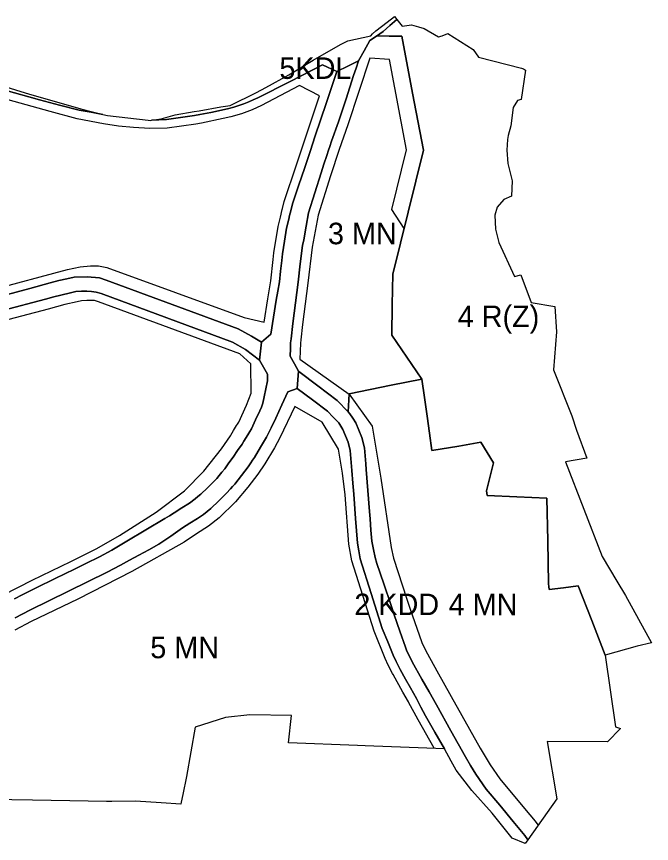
# Model space of a CAD drawing. Extents: x 7422252 to 7424226, y 5538569 to 5540380.
# Drawn here: x 7423783 to 7424226, y 5538929 to 5539505 of the extents above; entities that cross this region are included whole.
import ezdxf

# ---------------------------------------------------------------- set-up
doc = ezdxf.new("R2010")
doc.units = 0
for name, color, linetype in [('linie_rozgraniczajace', 7, 'Continuous'), ('linie_zabudowy_nieprzekraczalne', 7, 'Continuous'), ('oznaczenia_przeznaczen', 7, 'Continuous')]:
    doc.layers.add(name, color=color, linetype=linetype)

msp = doc.modelspace()

# ---------------------------------------------------------------- linework, layer by layer
at = {"layer": 'linie_rozgraniczajace'}
for points in [[(7423877.24, 5539432.91), (7423884.04, 5539433.94), (7423893.8, 5539436.72), (7423907.13, 5539439), (7423910.44, 5539439.57), (7423925.6, 5539442.23), (7423932.04, 5539443.25), (7423950.6, 5539452.2), (7423956.96, 5539455.69), (7423973.09, 5539464.55), (7423989.94, 5539474.71), (7424008.95, 5539485.69), (7424014.17, 5539488.19), (7424030.09, 5539491.68), (7424031.22, 5539493.04), (7424033.58, 5539495.28), (7424041.52, 5539501.38), (7424046.6, 5539505.19), (7424048.26, 5539503.12), (7424043.49, 5539498.95), (7424038.71, 5539494.78), (7424036.4, 5539493.2), (7424034.09, 5539491.61), (7424029.46, 5539488.45), (7424025.55, 5539481.36), (7424021.63, 5539474.27), (7424014.05, 5539470.55), (7424006.46, 5539466.83), (7423996.59, 5539471.45), (7423973.97, 5539460.04), (7423951.36, 5539448.64), (7423948.2, 5539447.17), (7423945.05, 5539445.7), (7423941.66, 5539444.42), (7423938.27, 5539443.13), (7423934.73, 5539442.15), (7423931.2, 5539441.18), (7423926.04, 5539439.92), (7423918.57, 5539438.38), (7423911.09, 5539436.83), (7423907.19, 5539436.17), (7423897.49, 5539434.75), (7423887.78, 5539433.34), (7423882.51, 5539433.13)], [(7424034.09, 5539491.61), (7424036.4, 5539493.2), (7424038.71, 5539494.78), (7424043.49, 5539498.95), (7424048.26, 5539503.12), (7424052.01, 5539498.44), (7424058.53, 5539499.41), (7424063.33, 5539498.06), (7424067.26, 5539496.94), (7424077.38, 5539491.11), (7424079.81, 5539491.64), (7424083.86, 5539493.27), (7424101.44, 5539482.17), (7424105.16, 5539476.82), (7424135.25, 5539469.27), (7424136.57, 5539468.64), (7424137.97, 5539467.89), (7424134.91, 5539447.36), (7424132.45, 5539446.59), (7424129.29, 5539441.9), (7424127.67, 5539429.1), (7424125.94, 5539422.32), (7424125.37, 5539419.48), (7424124.96, 5539412.17), (7424125.62, 5539402.78), (7424128.75, 5539390.8), (7424128.28, 5539379.93), (7424122.91, 5539377.72), (7424118.28, 5539372.37), (7424116.56, 5539366.83), (7424117.11, 5539357.13), (7424119.42, 5539347.81), (7424130.29, 5539324.12), (7424134.78, 5539325.3), (7424141.78, 5539306.02), (7424158.37, 5539303.13), (7424159.61, 5539285.56), (7424157.46, 5539259.07), (7424170.12, 5539227.02), (7424173.53, 5539216.86), (7424180.64, 5539197.37), (7424165.8, 5539195.01), (7424191.4, 5539128.84), (7424201.62, 5539111.65), (7424207.53, 5539101.69), (7424225.71, 5539068.74), (7424215.75, 5539066.44), (7424193.55, 5539060.17), (7424184.06, 5539084.3), (7424174.57, 5539108.42), (7424164.46, 5539107.21), (7424154.35, 5539106.01), (7424154.21, 5539108), (7424154.07, 5539110), (7424153.39, 5539139.85), (7424152.72, 5539169.7), (7424131.94, 5539170.57), (7424111.17, 5539171.43), (7424110.77, 5539174.68), (7424111.35, 5539177.51), (7424113.47, 5539185.9), (7424115.6, 5539194.29), (7424111.16, 5539201.46), (7424106.73, 5539208.62), (7424091.39, 5539205.92), (7424072.78, 5539202.9), (7424071.13, 5539214.87), (7424069.48, 5539226.84), (7424067.57, 5539239.68), (7424065.65, 5539252.53), (7424055.21, 5539267.88), (7424044.78, 5539283.22), (7424045.11, 5539304.41), (7424045.45, 5539325.59), (7424056.11, 5539368.85), (7424066.77, 5539412.1), (7424059.26, 5539451.8), (7424051.75, 5539491.49), (7424042.95, 5539491.57), (7424035.58, 5539491.63)], [(7423973.86, 5539268.46), (7423974.25, 5539273.94), (7423974.28, 5539277.87), (7423974.55, 5539280.73), (7423975.87, 5539291.33), (7423977.65, 5539305.74), (7423979.44, 5539320.16), (7423981.02, 5539332.92), (7423982.6, 5539345.68), (7423983.45, 5539349.61), (7423985.15, 5539359.04), (7423986.85, 5539368.46), (7423991.18, 5539382.32), (7423995.51, 5539396.19), (7423997.52, 5539402.3), (7423999.53, 5539408.42), (7424000.73, 5539412.05), (7424001.57, 5539414.6), (7424002.85, 5539418.39), (7424007.75, 5539431.82), (7424012.95, 5539447.92), (7424018.15, 5539464.02), (7424019.89, 5539469.14), (7424021.63, 5539474.27), (7424025.55, 5539481.36), (7424029.46, 5539488.45), (7424034.09, 5539491.61), (7424035.58, 5539491.63), (7424042.95, 5539491.57), (7424051.75, 5539491.49), (7424059.26, 5539451.8), (7424066.77, 5539412.1), (7424056.11, 5539368.85), (7424045.45, 5539325.59), (7424045.11, 5539304.41), (7424044.78, 5539283.22), (7424055.21, 5539267.88), (7424065.65, 5539252.53), (7424054.95, 5539250.4), (7424044.25, 5539248.27), (7424029.61, 5539245.24), (7424014.97, 5539242.21), (7424014.26, 5539229.79), (7424006.63, 5539237.75), (7423993.3, 5539247.78), (7423979.97, 5539257.81), (7423979.82, 5539258.07), (7423976.91, 5539263.13)], [(7423657.23, 5539474.02), (7423686.74, 5539473.68), (7423708.7, 5539472.45), (7423712.9, 5539472.22), (7423732.16, 5539469.42), (7423756.16, 5539462.25), (7423792.41, 5539451), (7423822.5, 5539442.43), (7423828.06, 5539440.87), (7423843.51, 5539437.03), (7423835.21, 5539438.46), (7423826.9, 5539439.88), (7423813.12, 5539443.52), (7423799.33, 5539447.16), (7423791.93, 5539449.21), (7423771.94, 5539454.76), (7423751.95, 5539460.31), (7423743.24, 5539462.01), (7423733.18, 5539463.45), (7423695.19, 5539468.74)], [(7423978.9, 5539246.04), (7423979.36, 5539252.04), (7423979.82, 5539258.07), (7423979.97, 5539257.81), (7423993.3, 5539247.78), (7424006.63, 5539237.75), (7424014.26, 5539229.79), (7424015.65, 5539228.33), (7424017.65, 5539225.22), (7424019.66, 5539222.1), (7424021.79, 5539216.94), (7424023.92, 5539211.78), (7424025.72, 5539204.56), (7424026.17, 5539199.09), (7424026.63, 5539193.63), (7424026.95, 5539189.66), (7424028.08, 5539174.97), (7424029.21, 5539160.27), (7424029.61, 5539155.08), (7424030.2, 5539147.36), (7424030.79, 5539139.65), (7424031.95, 5539133.91), (7424033.11, 5539128.17), (7424034.45, 5539124.12), (7424039.22, 5539109.83), (7424043.99, 5539095.54), (7424046.43, 5539088.3), (7424050.38, 5539077.01), (7424054.34, 5539065.71), (7424055.04, 5539063.7), (7424059.01, 5539055.6), (7424065.74, 5539043.55), (7424070.78, 5539034.53), (7424075.82, 5539025.51), (7424085.94, 5539007.4), (7424096.07, 5538989.29), (7424099.73, 5538983.28), (7424103.39, 5538977.27), (7424110.64, 5538966.77), (7424119.97, 5538955.56), (7424129.31, 5538944.35), (7424135.13, 5538937.37), (7424137.37, 5538934.44), (7424139.61, 5538931.52), (7424137.82, 5538928.99), (7424128.73, 5538932.59), (7424114.63, 5538950.18), (7424100.56, 5538965.99), (7424089.6, 5538980.09), (7424086.23, 5538986.23), (7424081.4, 5538995.03), (7424074.85, 5539006.52), (7424068.3, 5539018.01), (7424065.09, 5539023.96), (7424061.88, 5539029.91), (7424057.74, 5539037.38), (7424054.32, 5539043.5), (7424050.51, 5539050.31), (7424047.73, 5539055.89), (7424045.62, 5539060.21), (7424041.9, 5539069.52), (7424038.18, 5539078.83), (7424030.43, 5539103.11), (7424022.68, 5539127.38), (7424021.77, 5539132.83), (7424020.87, 5539138.28), (7424019.55, 5539155.38), (7424018.24, 5539172.48), (7424017.66, 5539180.11), (7424016.99, 5539188.87), (7424015.82, 5539202.92), (7424014.4, 5539208.64), (7424012.58, 5539213.05), (7424010.76, 5539217.45), (7424007.76, 5539222.11), (7424003.92, 5539226.12), (7424000.09, 5539230.13), (7423989.49, 5539238.09)], [(7424014.26, 5539229.79), (7424014.97, 5539242.21), (7424029.61, 5539245.24), (7424044.25, 5539248.27), (7424054.95, 5539250.4), (7424065.65, 5539252.53), (7424067.57, 5539239.68), (7424069.48, 5539226.84), (7424071.13, 5539214.87), (7424072.78, 5539202.9), (7424091.39, 5539205.92), (7424106.73, 5539208.62), (7424111.16, 5539201.46), (7424115.6, 5539194.29), (7424113.47, 5539185.9), (7424111.35, 5539177.51), (7424110.77, 5539174.68), (7424111.17, 5539171.43), (7424131.94, 5539170.57), (7424152.72, 5539169.7), (7424153.39, 5539139.85), (7424154.07, 5539110), (7424154.21, 5539108), (7424154.35, 5539106.01), (7424164.46, 5539107.21), (7424174.57, 5539108.42), (7424184.06, 5539084.3), (7424193.55, 5539060.17), (7424200.68, 5539010.35), (7424204.05, 5539008.98), (7424195.15, 5538999.8), (7424153.09, 5539000.01), (7424159.84, 5538960.08), (7424139.61, 5538931.52), (7424137.37, 5538934.44), (7424135.13, 5538937.37), (7424129.31, 5538944.35), (7424119.97, 5538955.56), (7424110.64, 5538966.77), (7424103.39, 5538977.27), (7424099.73, 5538983.28), (7424096.07, 5538989.29), (7424085.94, 5539007.4), (7424075.82, 5539025.51), (7424070.78, 5539034.53), (7424065.74, 5539043.55), (7424059.01, 5539055.6), (7424055.04, 5539063.7), (7424054.34, 5539065.71), (7424050.38, 5539077.01), (7424046.43, 5539088.3), (7424043.99, 5539095.54), (7424039.22, 5539109.83), (7424034.45, 5539124.12), (7424033.11, 5539128.17), (7424031.95, 5539133.91), (7424030.79, 5539139.65), (7424030.2, 5539147.36), (7424029.61, 5539155.08), (7424029.21, 5539160.27), (7424028.08, 5539174.97), (7424026.95, 5539189.66), (7424026.63, 5539193.63), (7424026.17, 5539199.09), (7424025.72, 5539204.56), (7424023.92, 5539211.78), (7424021.79, 5539216.94), (7424019.66, 5539222.1), (7424017.65, 5539225.22), (7424015.65, 5539228.33)]]:
    msp.add_lwpolyline(points, close=True, dxfattribs=at)
for points in [[(7423889.9, 5539157.39), (7423893.23, 5539159.38), (7423898.51, 5539162.8), (7423903.8, 5539166.22), (7423907.69, 5539169.15), (7423909.66, 5539170.72), (7423911.64, 5539172.28), (7423916.3, 5539176.83), (7423920.97, 5539181.38), (7423922.75, 5539183.38), (7423924.53, 5539185.37), (7423926.44, 5539187.72), (7423928.36, 5539190.07), (7423931.29, 5539194.12), (7423934.22, 5539198.17), (7423937.35, 5539202.72), (7423940.47, 5539207.27), (7423941.78, 5539209.36), (7423944.53, 5539213.69), (7423945.96, 5539215.93), (7423946.94, 5539217.79), (7423949.89, 5539224.09), (7423952.84, 5539230.4), (7423953.87, 5539233.03), (7423954.89, 5539235.68), (7423955.81, 5539240.16), (7423956.94, 5539245.74), (7423958.08, 5539251.31), (7423958.25, 5539256.09), (7423955.38, 5539260.97), (7423952.51, 5539265.85), (7423954.05, 5539278.31), (7423960.47, 5539283.95), (7423962.36, 5539295.72), (7423964.24, 5539307.48), (7423965.38, 5539313.86), (7423966.52, 5539320.24), (7423967.28, 5539327.74), (7423968.05, 5539335.23), (7423968.28, 5539337.52), (7423968.51, 5539339.8), (7423969.96, 5539348.78), (7423971.4, 5539357.77), (7423972.93, 5539363.96), (7423973.56, 5539366.5), (7423974.44, 5539369.84), (7423975.59, 5539374.6), (7423979.85, 5539387.26), (7423984.1, 5539399.92), (7423987.79, 5539411.05), (7423991.47, 5539422.18), (7423998.97, 5539444.51), (7424006.46, 5539466.83), (7424014.05, 5539470.55), (7424021.63, 5539474.27), (7424019.89, 5539469.14), (7424018.15, 5539464.02), (7424012.95, 5539447.92), (7424007.75, 5539431.82), (7424002.85, 5539418.39), (7424001.57, 5539414.6), (7424000.73, 5539412.05), (7423999.53, 5539408.42), (7423997.52, 5539402.3), (7423995.51, 5539396.19), (7423991.18, 5539382.32), (7423986.85, 5539368.46), (7423985.15, 5539359.04), (7423983.45, 5539349.61), (7423982.6, 5539345.68), (7423981.02, 5539332.92), (7423979.44, 5539320.16), (7423977.65, 5539305.74), (7423975.87, 5539291.33), (7423974.55, 5539280.73), (7423974.28, 5539277.87), (7423974.25, 5539273.94), (7423973.86, 5539268.46), (7423976.91, 5539263.13), (7423979.82, 5539258.07), (7423979.36, 5539252.04), (7423978.9, 5539246.04), (7423972.42, 5539243.75), (7423968.18, 5539234.52), (7423963.95, 5539225.29), (7423960.74, 5539218.71), (7423957.53, 5539212.12), (7423953.26, 5539205.08), (7423949, 5539198.04), (7423947.82, 5539196.09), (7423946.64, 5539194.15), (7423944.62, 5539191.53), (7423939.97, 5539185.48), (7423935.31, 5539179.42), (7423933.86, 5539177.81), (7423932.42, 5539176.19), (7423929.64, 5539173.08), (7423924.19, 5539167.77), (7423918.75, 5539162.45), (7423913.65, 5539158.13)], [(7423771.94, 5539454.76), (7423791.93, 5539449.21), (7423799.33, 5539447.16), (7423813.12, 5539443.52), (7423826.9, 5539439.88), (7423835.21, 5539438.46), (7423843.51, 5539437.03), (7423846.63, 5539436.26), (7423875.06, 5539432.93), (7423876.35, 5539432.78), (7423877.24, 5539432.91), (7423882.51, 5539433.13), (7423887.78, 5539433.34), (7423897.49, 5539434.75), (7423907.19, 5539436.17), (7423911.09, 5539436.83), (7423918.57, 5539438.38), (7423926.04, 5539439.92), (7423931.2, 5539441.18), (7423934.73, 5539442.15), (7423938.27, 5539443.13), (7423941.66, 5539444.42), (7423945.05, 5539445.7), (7423948.2, 5539447.17), (7423951.36, 5539448.64), (7423973.97, 5539460.04), (7423996.59, 5539471.45), (7424006.46, 5539466.83), (7423998.97, 5539444.51), (7423991.47, 5539422.18), (7423987.79, 5539411.05), (7423984.1, 5539399.92), (7423979.85, 5539387.26), (7423975.59, 5539374.6), (7423974.44, 5539369.84), (7423973.56, 5539366.5), (7423972.93, 5539363.96), (7423971.4, 5539357.77), (7423969.96, 5539348.78), (7423968.51, 5539339.8), (7423968.28, 5539337.52), (7423968.05, 5539335.23), (7423967.28, 5539327.74), (7423966.52, 5539320.24), (7423965.38, 5539313.86), (7423964.24, 5539307.48), (7423962.36, 5539295.72), (7423960.47, 5539283.95), (7423954.05, 5539278.31), (7423947.1, 5539282.53), (7423937.81, 5539287.66), (7423891.79, 5539304.53), (7423845.76, 5539321.4), (7423840.99, 5539323.07), (7423832.58, 5539323.91), (7423823.35, 5539323.56), (7423818.24, 5539322.39), (7423812.87, 5539321.16), (7423806.83, 5539319.53), (7423792.62, 5539315.59), (7423767.2, 5539308.99)], [(7423767.2, 5539308.99), (7423792.62, 5539315.59), (7423806.83, 5539319.53), (7423812.87, 5539321.16), (7423818.24, 5539322.39), (7423823.35, 5539323.56), (7423832.58, 5539323.91), (7423840.99, 5539323.07), (7423845.76, 5539321.4), (7423891.79, 5539304.53), (7423937.81, 5539287.66), (7423947.1, 5539282.53), (7423954.05, 5539278.31), (7423952.51, 5539265.85), (7423947.67, 5539269.49), (7423942.82, 5539273.13), (7423933.68, 5539278.24), (7423888.03, 5539295.17), (7423842.37, 5539312.1), (7423838.84, 5539313.23), (7423835.56, 5539313.56), (7423832.27, 5539313.89), (7423828.46, 5539313.75), (7423824.66, 5539313.6), (7423819.98, 5539312.53), (7423809.37, 5539309.86), (7423803.45, 5539308.26), (7423773.51, 5539300.39)], [(7423773.51, 5539300.39), (7423803.45, 5539308.26), (7423809.37, 5539309.86), (7423819.98, 5539312.53), (7423824.66, 5539313.6), (7423828.46, 5539313.75), (7423832.27, 5539313.89), (7423835.56, 5539313.56), (7423838.84, 5539313.23), (7423842.37, 5539312.1), (7423888.03, 5539295.17), (7423933.68, 5539278.24), (7423942.82, 5539273.13), (7423947.67, 5539269.49), (7423952.51, 5539265.85), (7423955.38, 5539260.97), (7423958.25, 5539256.09), (7423958.08, 5539251.31), (7423956.94, 5539245.74), (7423955.81, 5539240.16), (7423954.89, 5539235.68), (7423953.87, 5539233.03), (7423952.84, 5539230.4), (7423949.89, 5539224.09), (7423946.94, 5539217.79), (7423945.96, 5539215.93), (7423944.53, 5539213.69), (7423941.78, 5539209.36), (7423940.47, 5539207.27), (7423937.35, 5539202.72), (7423934.22, 5539198.17), (7423931.29, 5539194.12), (7423928.36, 5539190.07), (7423926.44, 5539187.72), (7423924.53, 5539185.37), (7423922.75, 5539183.38), (7423920.97, 5539181.38), (7423916.3, 5539176.83), (7423911.64, 5539172.28), (7423909.66, 5539170.72), (7423907.69, 5539169.15), (7423903.8, 5539166.22), (7423898.51, 5539162.8), (7423893.23, 5539159.38), (7423889.9, 5539157.39), (7423886.56, 5539155.39), (7423873.4, 5539147.51), (7423860.24, 5539139.64), (7423849.7, 5539133.33), (7423841.06, 5539128.66), (7423831.63, 5539124.05), (7423827.82, 5539122.18), (7423823.66, 5539120.15), (7423810.3, 5539113.61), (7423796.94, 5539107.07), (7423787.25, 5539102.33), (7423781.77, 5539099.5)], [(7423782.37, 5539086.3), (7423792.64, 5539091.6), (7423819.59, 5539104.8), (7423846.55, 5539117.99), (7423855.64, 5539122.9), (7423862.06, 5539126.39), (7423868.48, 5539129.88), (7423875.5, 5539133.7), (7423882.51, 5539137.52), (7423890.75, 5539143.18), (7423898.98, 5539148.84), (7423904.16, 5539152.11), (7423909.35, 5539155.38), (7423913.65, 5539158.13), (7423918.75, 5539162.45), (7423924.19, 5539167.77), (7423929.64, 5539173.08), (7423932.42, 5539176.19), (7423933.86, 5539177.81), (7423935.31, 5539179.42), (7423939.97, 5539185.48), (7423944.62, 5539191.53), (7423946.64, 5539194.15), (7423947.82, 5539196.09), (7423949, 5539198.04), (7423953.26, 5539205.08), (7423957.53, 5539212.12), (7423960.74, 5539218.71), (7423963.95, 5539225.29), (7423968.18, 5539234.52), (7423972.42, 5539243.75), (7423978.9, 5539246.04), (7423989.49, 5539238.09), (7424000.09, 5539230.13), (7424003.92, 5539226.12), (7424007.76, 5539222.11), (7424010.76, 5539217.45), (7424012.58, 5539213.05), (7424014.4, 5539208.64), (7424015.82, 5539202.92), (7424016.99, 5539188.87), (7424017.66, 5539180.11), (7424018.24, 5539172.48), (7424019.55, 5539155.38), (7424020.87, 5539138.28), (7424021.77, 5539132.83), (7424022.68, 5539127.38), (7424030.43, 5539103.11), (7424038.18, 5539078.83), (7424041.9, 5539069.52), (7424045.62, 5539060.21), (7424047.73, 5539055.89), (7424050.51, 5539050.31), (7424054.32, 5539043.5), (7424057.74, 5539037.38), (7424061.88, 5539029.91), (7424065.09, 5539023.96), (7424068.3, 5539018.01), (7424074.85, 5539006.52), (7424081.4, 5538995.03), (7424026.22, 5538997.11), (7424020.83, 5538997.35), (7423972.87, 5538999.05), (7423974.82, 5539018.19), (7423945.91, 5539018.71), (7423928.83, 5539016.73), (7423907.8, 5539010.1), (7423901.76, 5538975.63), (7423899.08, 5538963.1), (7423898.03, 5538957.76), (7423897.73, 5538956.3), (7423883.98, 5538957.19), (7423866.26, 5538958.35), (7423849.63, 5538958.25), (7423845.94, 5538958.31), (7423820.54, 5538958.74), (7423794.47, 5538959.18), (7423765.5, 5538959.66)], [(7423781.77, 5539099.5), (7423787.25, 5539102.33), (7423796.94, 5539107.07), (7423810.3, 5539113.61), (7423823.66, 5539120.15), (7423827.82, 5539122.18), (7423831.63, 5539124.05), (7423841.06, 5539128.66), (7423849.7, 5539133.33), (7423860.24, 5539139.64), (7423873.4, 5539147.51), (7423886.56, 5539155.39), (7423889.9, 5539157.39)], [(7423913.65, 5539158.13), (7423909.35, 5539155.38), (7423904.16, 5539152.11), (7423898.98, 5539148.84), (7423890.75, 5539143.18), (7423882.51, 5539137.52), (7423875.5, 5539133.7), (7423868.48, 5539129.88), (7423862.06, 5539126.39), (7423855.64, 5539122.9), (7423846.55, 5539117.99), (7423819.59, 5539104.8), (7423792.64, 5539091.6), (7423782.37, 5539086.3)]]:
    msp.add_lwpolyline(points, dxfattribs=at)
at = {"layer": 'linie_zabudowy_nieprzekraczalne'}
for points in [[(7424053.32, 5539357.51), (7424044.69, 5539370.75), (7424054.99, 5539412.42), (7424054.99, 5539412.42), (7424043.17, 5539475.15), (7424029.45, 5539476.24), (7424029.45, 5539476.24), (7424014.16, 5539429.62), (7424008.04, 5539412.6), (7424008.04, 5539412.6), (7424008.04, 5539412.6), (7424008.04, 5539412.6), (7424001.96, 5539394.12), (7423993.44, 5539366.85), (7423989.28, 5539344.55), (7423989.28, 5539344.55), (7423989.28, 5539344.55), (7423986.16, 5539319.32), (7423982.59, 5539290.5), (7423981.29, 5539280), (7423981.06, 5539277.53), (7423981.06, 5539277.53), (7423980.67, 5539266.44), (7423980.67, 5539266.44), (7423980.67, 5539266.44), (7423980.67, 5539266.44), (7424014.97, 5539242.16), (7424014.97, 5539242.16), (7424031.06, 5539219.77), (7424031.06, 5539219.77), (7424031.06, 5539219.77), (7424031.06, 5539219.77), (7424037.23, 5539183.49), (7424037.23, 5539183.49), (7424044.29, 5539135.11), (7424044.29, 5539135.11), (7424044.29, 5539135.11), (7424045.92, 5539127.88), (7424055.26, 5539099.32), (7424057.67, 5539092.17), (7424065.56, 5539069.64), (7424066.03, 5539068.29), (7424069.54, 5539061.12), (7424076.12, 5539049.35), (7424086.2, 5539031.31), (7424106.34, 5538995.28), (7424113.37, 5538983.74), (7424120.12, 5538973.97), (7424138.44, 5538951.96), (7424143.49, 5538945.9), (7424144.42, 5538944.79), (7424146.8, 5538941.68)], [(7423764.98, 5539314.61), (7423818.79, 5539328.98), (7423827.59, 5539330.69), (7423834.77, 5539331.59), (7423840.35, 5539331.51), (7423846.24, 5539330.34), (7423941.84, 5539295.38), (7423955.73, 5539292.19), (7423958.33, 5539308.48), (7423960.57, 5539321.07), (7423962.08, 5539335.84), (7423962.56, 5539340.58), (7423965.51, 5539358.96), (7423967.11, 5539365.4), (7423968.41, 5539370.66), (7423968.65, 5539371.44), (7423969.82, 5539376.27), (7423978.41, 5539401.82), (7423985.78, 5539424.08), (7423994.49, 5539450.02), (7423980.5, 5539457.1), (7423957.93, 5539445.38), (7423954.05, 5539443.28), (7423947.38, 5539440.17), (7423940.13, 5539437.43), (7423932.7, 5539435.37), (7423927.36, 5539434.07), (7423912.2, 5539430.94), (7423908.13, 5539430.24), (7423888.34, 5539427.36), (7423876.15, 5539427.16), (7423864.71, 5539427.84), (7423854.42, 5539428.85), (7423843.94, 5539430.47), (7423825.65, 5539434.01), (7423806.71, 5539439.01), (7423756.27, 5539452.89)], [(7423773.26, 5539101.85), (7423784.55, 5539107.69), (7423794.3, 5539112.46), (7423821.02, 5539125.53), (7423821.02, 5539125.53), (7423821.02, 5539125.53), (7423839.36, 5539134.58), (7423854.98, 5539143.48), (7423854.98, 5539143.48), (7423880.5, 5539159.88), (7423880.5, 5539159.88), (7423880.5, 5539159.88), (7423900.36, 5539174.71), (7423900.36, 5539174.71), (7423913.72, 5539188.32), (7423913.72, 5539188.32), (7423926.02, 5539203.95), (7423926.02, 5539203.95), (7423926.02, 5539203.95), (7423932.32, 5539213.11), (7423932.61, 5539213.5), (7423934.51, 5539216.65), (7423935.22, 5539217.82), (7423936.61, 5539220.11), (7423937.27, 5539221.19), (7423938.08, 5539222.53), (7423943.61, 5539234.34), (7423945.24, 5539238.51), (7423946.77, 5539242.69), (7423946.57, 5539263.09), (7423938.95, 5539270.12), (7423938.95, 5539270.12), (7423840.41, 5539306.43), (7423837.62, 5539307.33), (7423836.81, 5539307.41), (7423832.3, 5539307.43), (7423828.67, 5539307.08), (7423825.61, 5539306.47), (7423817.03, 5539304.5), (7423805.3, 5539301.34), (7423744.98, 5539285.49)], [(7424074.34, 5538995.3), (7424063.06, 5539015.1), (7424056.4, 5539027.42), (7424056.34, 5539027.58), (7424052.5, 5539034.46), (7424045.66, 5539046.69), (7424045.21, 5539047.51), (7424042.35, 5539053.24), (7424040.13, 5539057.78), (7424032.53, 5539076.81), (7424016.84, 5539125.97), (7424014.9, 5539137.55), (7424012.26, 5539172.02), (7424010.51, 5539187.02), (7424007.63, 5539203.76), (7423996.37, 5539222.47), (7423977.22, 5539233.42), (7423977.22, 5539233.42), (7423966.81, 5539211.59), (7423963.14, 5539204.73), (7423956.38, 5539193.57), (7423951.5, 5539186.25), (7423944.46, 5539177.17), (7423935.88, 5539167.11), (7423924.38, 5539155.9), (7423917.06, 5539150.09), (7423908.67, 5539144.74), (7423900.01, 5539138.9), (7423863.56, 5539118.45), (7423826.04, 5539099.24), (7423793.46, 5539083.76), (7423782.18, 5539077.6)]]:
    msp.add_lwpolyline(points, dxfattribs=at)

# ---------------------------------------------------------------- texts
at = {"layer": 'oznaczenia_przeznaczen'}
for s, p in [('5KDL', (7423966.46, 5539461.74)), ('3 MN', (7424000.3, 5539346.52)), ('4 R(Z)', (7424090.72, 5539288.77)), ('2 KDD', (7424018.69, 5539088.08)), ('4 MN', (7424084.39, 5539088.04)), ('5 MN', (7423876.49, 5539058.06))]:
    msp.add_text(s, height=15, dxfattribs=at).set_placement(p)

doc.saveas('drawing.dxf')
